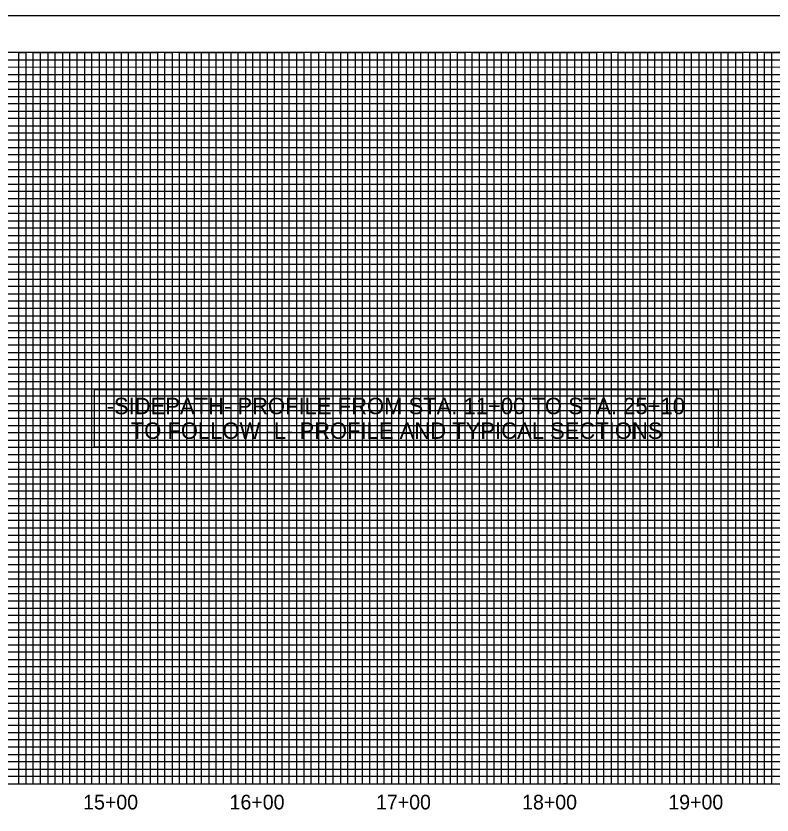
# Model space of a CAD drawing. Extents: x 1524869 to 1526553, y 501099 to 502199.
# Drawn here: x 1525519 to 1526036, y 501652 to 502199 of the extents above; entities that cross this region are included whole.
import ezdxf

# ---------------------------------------------------------------- set-up
doc = ezdxf.new("R2010")
doc.units = 0
for name, color, linetype in [('Exist Vertical Profile Horizontal Axis Label Major', 7, 'Continuous'), ('Prop Grid Mask', 7, 'Continuous'), ('Prop Horizontal Alignment Curve and Spiral Data', 7, 'Continuous'), ('Sheet Layout Profile Border Port 1', 7, 'Continuous'), ('Sheet Plot Border Outside CELL', 7, 'Continuous'), ('Sheet Profile CELL', 7, 'Continuous'), ('Sheet Profile Grid Major CELL', 7, 'Continuous'), ('Sheet Profile Grid Middle CELL', 7, 'Continuous'), ('Sheet Profile Grid Minor CELL', 7, 'Continuous')]:
    doc.layers.add(name, color=color, linetype=linetype)

msp = doc.modelspace()

# ---------------------------------------------------------------- linework, layer by layer
at = {"layer": 'Prop Grid Mask'}
msp.add_lwpolyline([(1525572.71, 501903.97), (1525999.46, 501903.97), (1525999.46, 501943.01), (1525572.71, 501943.01)], close=True, dxfattribs=at)
at = {"layer": 'Sheet Layout Profile Border Port 1'}
msp.add_lwpolyline([(1525086.08, 502173.56), (1525086.08, 501673.56), (1526486.08, 501673.56), (1526486.08, 502012.51), (1526336.03, 502012.51), (1526336.08, 502173.56)], close=True, dxfattribs=at)
at = {"layer": 'Sheet Plot Border Outside CELL'}
msp.add_lwpolyline([(1524869.08, 501098.56), (1526553.08, 501098.56), (1526553.08, 502198.56), (1524869.08, 502198.56)], close=True, dxfattribs=at)
at = {"layer": 'Sheet Profile CELL'}
msp.add_line((1525036.08, 501673.56), (1526536.08, 501673.56), dxfattribs=at)
msp.add_lwpolyline([(1526536.08, 502173.56), (1525036.08, 502173.56), (1525036.08, 501123.56), (1526536.08, 501123.56)], close=True, dxfattribs=at)
at = {"layer": 'Sheet Profile Grid Major CELL'}
for points in [[(1525486.08, 501673.56), (1525536.08, 501673.56), (1525536.08, 502173.56), (1525586.08, 502173.56), (1525586.08, 501673.56), (1525636.08, 501673.56), (1525636.08, 502173.56), (1525686.08, 502173.56), (1525686.08, 501673.56), (1525736.08, 501673.56), (1525736.08, 502173.56), (1525786.08, 502173.56), (1525786.08, 501673.56), (1525836.08, 501673.56), (1525836.08, 502173.56), (1525886.08, 502173.56), (1525886.08, 501673.56), (1525936.08, 501673.56), (1525936.08, 502173.56), (1525986.08, 502173.56), (1525986.08, 501673.56), (1526036.08, 501673.56), (1526036.08, 502173.56), (1526086.08, 502173.56)], [(1525036.08, 502123.56), (1526336.08, 502123.56)], [(1526336.08, 502073.56), (1525036.08, 502073.56), (1525036.08, 502023.56), (1526336.08, 502023.56)], [(1526536.08, 501973.56), (1525036.08, 501973.56), (1525036.08, 501923.56), (1526536.08, 501923.56)], [(1526536.08, 501873.56), (1525036.08, 501873.56), (1525036.08, 501823.56), (1526536.08, 501823.56)], [(1526536.08, 501773.56), (1525036.08, 501773.56), (1525036.08, 501773.56), (1525036.08, 501723.56), (1526536.08, 501723.56)]]:
    msp.add_lwpolyline(points, dxfattribs=at)
at = {"layer": 'Sheet Profile Grid Middle CELL'}
msp.add_line((1525036.08, 502148.56), (1526336.03, 502148.56), dxfattribs=at)
for points in [[(1525511.08, 501673.56), (1525561.08, 501673.56), (1525561.08, 502173.56), (1525611.08, 502173.56), (1525611.08, 501673.56), (1525661.08, 501673.56), (1525661.08, 501673.56), (1525661.08, 502173.56), (1525711.08, 502173.56), (1525711.08, 501673.56), (1525761.08, 501673.56), (1525761.08, 502173.56), (1525811.08, 502173.56), (1525811.08, 501673.56), (1525861.08, 501673.56), (1525861.08, 502173.56), (1525911.08, 502173.56), (1525911.08, 501673.56), (1525961.08, 501673.56), (1525961.08, 502173.56), (1526011.08, 502173.56), (1526011.08, 501673.56), (1526061.08, 501673.56)], [(1526336.08, 502098.56), (1525036.08, 502098.56), (1525036.08, 502048.56), (1526336.08, 502048.56)], [(1526536.08, 501998.56), (1525036.08, 501998.56), (1525036.08, 501948.56), (1526361.08, 501948.56)], [(1526536.08, 501898.56), (1525036.08, 501898.56), (1525036.08, 501848.56), (1526536.08, 501848.56)], [(1526536.08, 501798.56), (1525036.08, 501798.56), (1525036.08, 501748.56), (1526536.08, 501748.56)], [(1526536.08, 501698.56), (1525036.08, 501698.56)]]:
    msp.add_lwpolyline(points, dxfattribs=at)
at = {"layer": 'Sheet Profile Grid Minor CELL'}
for p, q in [((1525086.08, 502168.56), (1526336.08, 502168.56)), ((1526336.08, 502163.56), (1525086.08, 502163.21)), ((1525086.08, 502158.56), (1526336.08, 502158.56)), ((1526336.03, 502038.56), (1525086.08, 502038.56)), ((1526336.08, 502033.56), (1525086.08, 502033.56)), ((1526336.08, 502028.56), (1525086.08, 502028.56)), ((1525086.08, 502018.56), (1526336.08, 502018.56)), ((1526336.08, 502013.56), (1525086.08, 502013.56)), ((1525086.08, 502008.56), (1526486.08, 502008.56)), ((1526486.08, 501988.56), (1525086.08, 501988.56)), ((1525086.08, 501983.56), (1526486.08, 501983.56)), ((1526486.08, 501963.56), (1525086.08, 501963.56)), ((1525086.08, 501958.56), (1526486.08, 501958.56)), ((1526486.08, 501938.56), (1525086.08, 501938.56)), ((1525086.08, 501933.56), (1526486.08, 501933.56)), ((1525695.6, 501933.01), (1525695.6, 501933.01)), ((1525695.6, 501933.01), (1525695.6, 501933.01)), ((1526486.08, 501928.56), (1525086.08, 501928.56)), ((1525086.08, 501918.56), (1526486.08, 501918.56)), ((1526486.08, 501913.56), (1525086.08, 501913.56)), ((1525086.08, 501908.56), (1526486.08, 501908.56)), ((1526486.08, 501903.56), (1525086.08, 501903.56)), ((1525086.08, 501893.56), (1526486.08, 501893.56)), ((1526486.08, 501888.56), (1525086.08, 501888.56)), ((1525086.08, 501883.56), (1526486.08, 501883.56)), ((1526486.08, 501878.56), (1525086.08, 501878.56)), ((1525086.08, 501868.56), (1526486.08, 501868.56)), ((1526486.08, 501863.56), (1525086.08, 501863.56)), ((1525086.08, 501858.56), (1526486.08, 501858.56)), ((1526486.08, 501853.56), (1525086.08, 501853.56)), ((1525086.08, 501843.56), (1526486.08, 501843.56)), ((1526486.08, 501838.56), (1525086.08, 501838.56)), ((1525086.08, 501833.56), (1526486.08, 501833.56)), ((1526486.08, 501828.56), (1525086.08, 501828.56)), ((1525086.08, 501818.56), (1526486.08, 501818.56)), ((1526486.08, 501813.56), (1525086.08, 501813.56)), ((1525086.08, 501808.56), (1526486.08, 501808.56)), ((1526486.08, 501803.56), (1525086.08, 501803.56)), ((1525086.08, 501793.56), (1526486.08, 501793.56)), ((1526486.08, 501788.56), (1525086.08, 501788.56)), ((1526486.08, 501783.56), (1525086.08, 501783.56)), ((1526486.08, 501778.56), (1525086.08, 501778.56)), ((1525086.08, 501768.56), (1526486.08, 501768.56)), ((1526486.08, 501763.56), (1525086.08, 501763.56)), ((1525086.08, 501758.56), (1526486.08, 501758.56)), ((1526486.08, 501753.56), (1525086.08, 501753.56)), ((1525086.08, 501743.56), (1526486.08, 501743.56)), ((1526486.08, 501738.56), (1525086.08, 501738.56)), ((1525086.08, 501733.56), (1526486.08, 501733.56)), ((1526486.08, 501728.56), (1525086.08, 501728.56)), ((1525086.08, 501718.56), (1526486.08, 501718.56)), ((1526486.08, 501713.56), (1525086.08, 501713.56)), ((1525086.08, 501708.56), (1526486.08, 501708.56)), ((1526486.08, 501703.56), (1525086.08, 501703.56)), ((1525086.08, 501693.56), (1526486.08, 501693.56)), ((1526486.08, 501688.56), (1525086.08, 501688.56)), ((1525086.08, 501683.56), (1526486.08, 501683.56))]:
    msp.add_line(p, q, dxfattribs=at)
for points in [[(1525516.08, 501673.56), (1525521.08, 501673.56), (1525521.08, 502173.56), (1525526.08, 502173.56), (1525526.08, 501673.56), (1525531.08, 501673.56), (1525531.08, 502173.56), (1525541.08, 502173.56), (1525541.08, 501673.56), (1525546.08, 501673.56), (1525546.08, 502173.56), (1525551.08, 502173.56), (1525551.08, 501673.56), (1525556.08, 501673.56), (1525556.08, 502173.56), (1525566.08, 502173.56), (1525566.08, 501673.56), (1525571.08, 501673.56), (1525571.08, 502173.56), (1525576.08, 502173.56), (1525576.08, 501673.56), (1525581.08, 501673.56), (1525581.08, 502173.56), (1525591.08, 502173.56), (1525591.08, 501673.56), (1525596.08, 501673.56), (1525596.08, 502173.56), (1525601.08, 502173.56), (1525601.08, 501673.56), (1525606.08, 501673.56), (1525606.08, 502173.56), (1525616.08, 502173.56)], [(1525616.08, 502173.56), (1525616.08, 501673.56), (1525621.08, 501673.56), (1525621.08, 502173.56), (1525626.08, 502173.56), (1525626.08, 501673.56), (1525631.08, 501673.56), (1525631.08, 502173.56), (1525641.08, 502173.56), (1525641.08, 501673.56), (1525646.08, 501673.56), (1525646.08, 502173.56), (1525651.08, 502173.56), (1525651.08, 501673.56), (1525656.08, 501673.56), (1525656.08, 502173.56), (1525666.08, 502173.56), (1525666.08, 501673.56), (1525671.08, 501673.56), (1525671.08, 502173.56), (1525676.08, 502173.56), (1525676.08, 501673.56), (1525681.08, 501673.56), (1525681.08, 502173.56), (1525691.08, 502173.56), (1525691.08, 501673.56), (1525696.08, 501673.56), (1525696.08, 502173.56), (1525701.08, 502173.56), (1525701.08, 501673.56), (1525706.08, 501673.56), (1525706.08, 502173.56), (1525716.08, 502173.56), (1525716.08, 501673.56), (1525721.08, 501673.56), (1525721.08, 502173.56), (1525726.08, 502173.56), (1525726.08, 501673.56), (1525731.08, 501673.56), (1525731.08, 502173.56), (1525741.08, 502173.56), (1525741.08, 501673.56), (1525741.08, 501673.56), (1525746.08, 501673.56), (1525746.08, 502173.56), (1525751.08, 502173.56), (1525751.08, 501673.56), (1525756.08, 501673.56), (1525756.08, 502173.56), (1525766.08, 502173.56), (1525766.08, 501673.56), (1525771.08, 501673.56), (1525771.08, 502173.56), (1525776.08, 502173.56), (1525776.08, 501673.56), (1525781.08, 501673.56), (1525781.08, 502173.56), (1525791.08, 502173.56), (1525791.08, 501673.56), (1525796.08, 501673.56), (1525796.08, 502173.56), (1525801.08, 502173.56), (1525801.08, 501673.56), (1525806.08, 501673.56), (1525806.08, 502173.56), (1525816.08, 502173.56), (1525816.08, 501673.56), (1525821.08, 501673.56), (1525821.08, 502173.56), (1525826.08, 502173.56), (1525826.08, 501673.56), (1525831.08, 501673.56), (1525831.08, 502173.56), (1525841.08, 502173.56), (1525841.08, 501673.56), (1525846.08, 501673.56), (1525846.08, 502173.56), (1525851.08, 502173.56), (1525851.08, 501673.56), (1525856.08, 501673.56), (1525856.08, 502173.56), (1525866.08, 502173.56), (1525866.08, 501673.56), (1525871.08, 501673.56), (1525871.08, 502173.56), (1525876.08, 502173.56), (1525876.08, 501673.56), (1525881.08, 501673.56), (1525881.08, 502173.56), (1525891.08, 502173.56), (1525891.08, 501673.56), (1525895.78, 501674.11), (1525896.08, 501673.56), (1525896.08, 502173.56), (1525901.08, 502173.56), (1525901.08, 501673.56), (1525906.08, 501673.56), (1525906.08, 502173.56), (1525916.08, 502173.56), (1525916.08, 501673.56), (1525921.08, 501673.56)], [(1525921.08, 501673.56), (1525921.08, 502173.56), (1525926.08, 502173.56), (1525926.08, 501673.56), (1525931.08, 501673.56), (1525931.08, 502173.56), (1525941.08, 502173.56), (1525941.08, 501673.56), (1525946.08, 501673.56), (1525946.08, 502173.56), (1525951.08, 502173.56), (1525951.08, 501673.56), (1525956.08, 501673.56), (1525956.08, 502173.56), (1525966.08, 502173.56), (1525966.08, 501673.56), (1525971.08, 501673.56), (1525971.08, 502173.56), (1525976.08, 502173.56), (1525976.08, 501673.56), (1525981.08, 501673.56), (1525981.08, 502173.56), (1525991.08, 502173.56), (1525991.08, 501673.56), (1525996.08, 501673.56), (1525996.08, 502173.56), (1526001.08, 502173.56), (1526001.08, 501673.56), (1526006.08, 501673.56), (1526006.08, 502173.56), (1526016.08, 502173.56), (1526016.08, 501673.56), (1526021.08, 501673.56), (1526021.08, 502173.56), (1526026.08, 502173.56), (1526026.08, 501673.56), (1526031.08, 501673.56), (1526031.08, 502173.56), (1526041.08, 502173.56)], [(1526336.08, 502153.56), (1525086.08, 502153.56), (1525086.08, 502143.56), (1526336.08, 502143.56)], [(1526336.03, 502138.56), (1525086.08, 502138.56), (1525086.08, 502133.56), (1526336.08, 502133.56)], [(1526336.08, 502128.56), (1525086.08, 502128.56), (1525086.08, 502118.56), (1526336.08, 502118.56)], [(1526336.08, 502113.56), (1525086.08, 502113.56), (1525086.08, 502108.56), (1526336.08, 502108.56)], [(1526336.08, 502103.56), (1525086.08, 502103.56), (1525086.08, 502093.56), (1526336.08, 502093.56)], [(1526336.08, 502088.56), (1525086.08, 502088.56), (1525086.08, 502083.56), (1526336.08, 502083.56)], [(1526336.08, 502078.56), (1525086.08, 502078.56), (1525086.08, 502068.56), (1526336.08, 502068.56)], [(1526336.08, 502063.46), (1525086.18, 502063.46), (1525086.18, 502058.56), (1526336.08, 502058.56)], [(1526336.08, 502053.56), (1525086.08, 502053.56), (1525086.08, 502043.56), (1526336.08, 502043.56)], [(1526486.08, 502003.56), (1525086.08, 502003.56), (1525086.08, 501993.56), (1526486.08, 501993.56)], [(1526486.08, 501978.56), (1525086.08, 501978.56), (1525086.08, 501968.56), (1526486.08, 501968.56)], [(1526486.08, 501953.56), (1525086.08, 501953.56), (1525086.08, 501943.56), (1526486.08, 501943.56)], [(1526486.08, 501678.56), (1525086.08, 501678.56)]]:
    msp.add_lwpolyline(points, dxfattribs=at)

# ---------------------------------------------------------------- texts
at = {"layer": 'Exist Vertical Profile Horizontal Axis Label Major'}
for s, p in [('15+00', (1525565.17, 501656.06)), ('16+00', (1525665.28, 501656.06)), ('17+00', (1525765.39, 501656.06)), ('18+00', (1525865.28, 501656.06)), ('19+00', (1525965.25, 501656.06))]:
    msp.add_text(s, height=10, dxfattribs=at).set_placement(p)
at = {"layer": 'Prop Horizontal Alignment Curve and Spiral Data'}
for s, p in [('-SIDEPATH- PROFILE FROM STA. 11+00 TO STA. 25+10', (1525581.2, 501926.3)), ('TO FOLLOW -L- PROFILE AND TYPICAL SECTIONS', (1525597.69, 501909.43))]:
    msp.add_text(s, height=11.25, rotation=360, dxfattribs=at).set_placement(p)

doc.saveas('drawing.dxf')
